Omron CX-Programmer project 新工程 (CX-Programmer 7.30)

# PLC 欧姆龙CP1H: CP1H X

## Global symbols (name address type ; comment)
D0 CHANNEL  ; 设定频率参考值
D1 CHANNEL  ; 设定加速时间1高字
D10 CHANNEL  ; 当前频率值-低字
D11 CHANNEL  ; 当前频率值-高字
D12 CHANNEL  ; 当前电流值
D2 CHANNEL  ; 设定加速时间1低字
D20 CHANNEL  ; 控制字

## Program 新程序1 (cyclic task 0)

### Section 段1

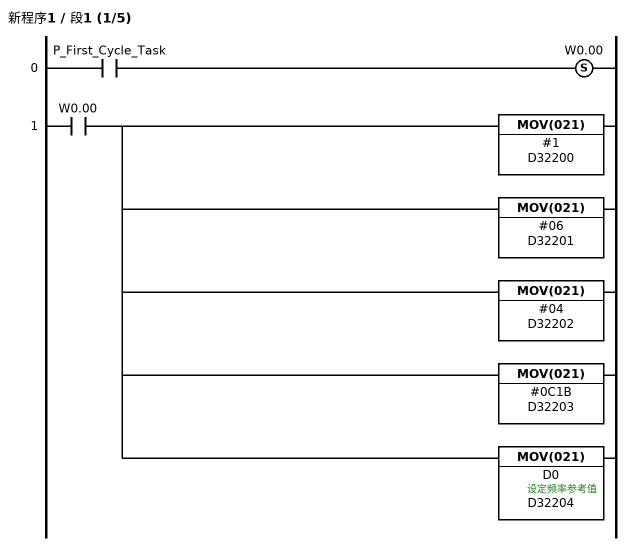
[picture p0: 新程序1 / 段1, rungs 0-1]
; rung 0
LD P_First_Cycle_Task
SET W0.00
; rung 1
LD W0.00
MOV(021) #1 D32200
MOV(021) #06 D32201
MOV(021) #04 D32202
MOV(021) #0C1B D32203
MOV(021) D0 D32204  ; 设定频率参考值

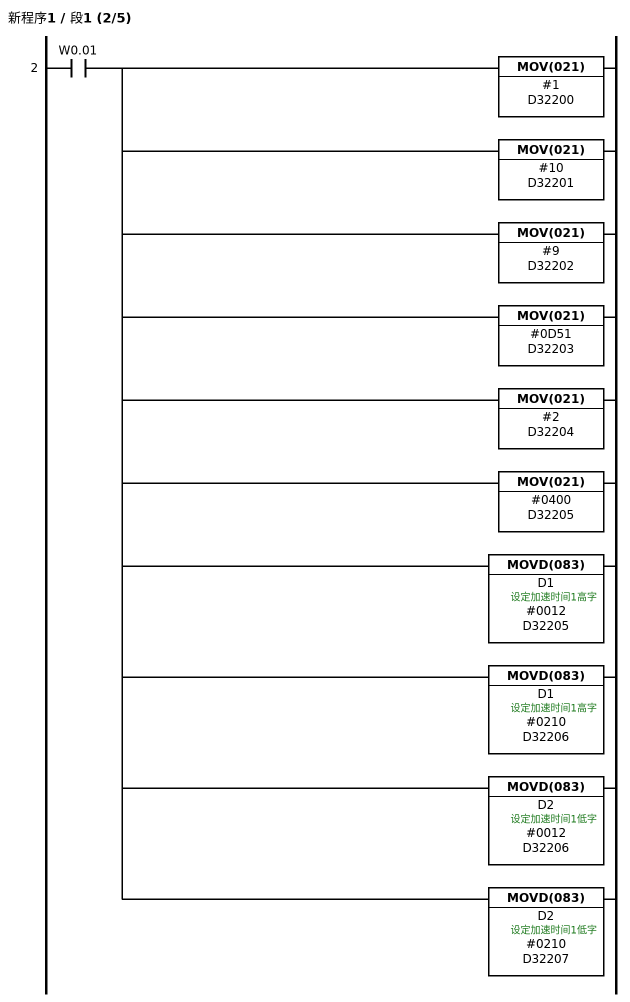
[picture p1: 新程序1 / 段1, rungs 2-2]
; rung 2
LD W0.01
MOV(021) #1 D32200
MOV(021) #10 D32201
MOV(021) #9 D32202
MOV(021) #0D51 D32203
MOV(021) #2 D32204
MOV(021) #0400 D32205
MOVD(083) D1 #0012 D32205  ; 设定加速时间1高字
MOVD(083) D1 #0210 D32206  ; 设定加速时间1高字
MOVD(083) D2 #0012 D32206  ; 设定加速时间1低字
MOVD(083) D2 #0210 D32207  ; 设定加速时间1低字

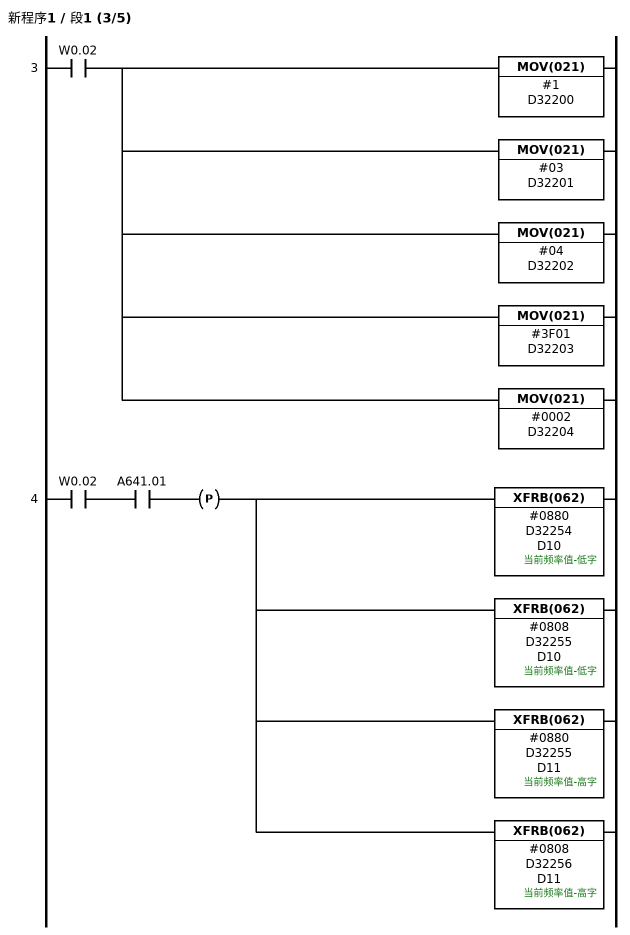
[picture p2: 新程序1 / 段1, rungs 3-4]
; rung 3
LD W0.02
MOV(021) #1 D32200
MOV(021) #03 D32201
MOV(021) #04 D32202
MOV(021) #3F01 D32203
MOV(021) #0002 D32204
; rung 4
LD W0.02
AND A641.01
UP(521)
XFRB(062) #0880 D32254 D10  ; 当前频率值-低字
XFRB(062) #0808 D32255 D10  ; 当前频率值-低字
XFRB(062) #0880 D32255 D11  ; 当前频率值-高字
XFRB(062) #0808 D32256 D11  ; 当前频率值-高字

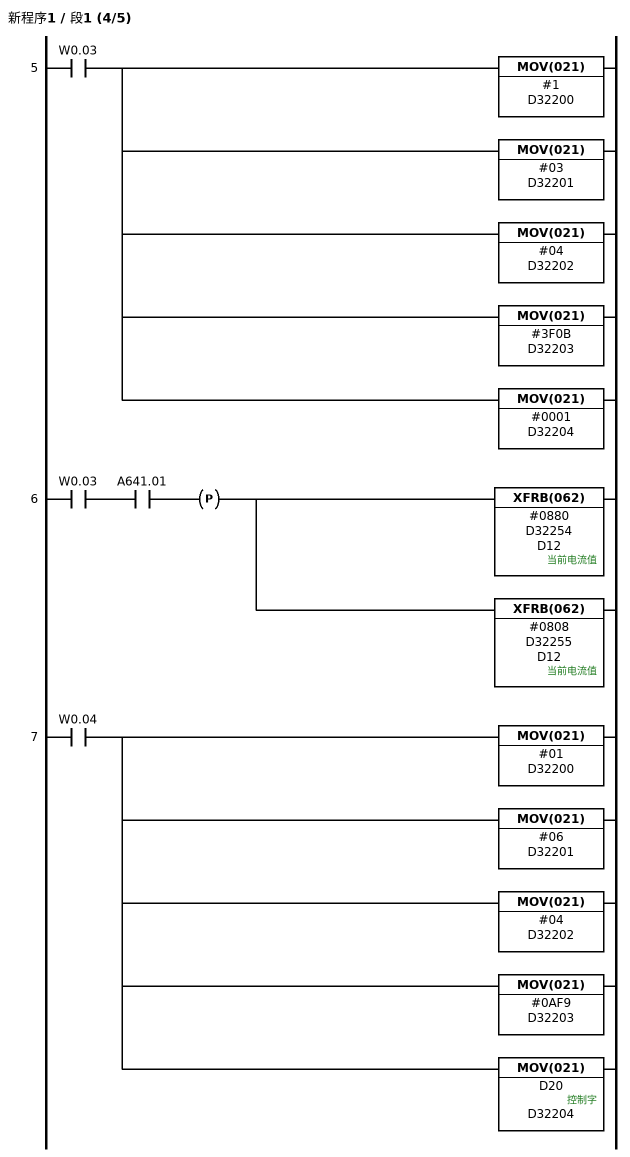
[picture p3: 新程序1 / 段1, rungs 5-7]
; rung 5
LD W0.03
MOV(021) #1 D32200
MOV(021) #03 D32201
MOV(021) #04 D32202
MOV(021) #3F0B D32203
MOV(021) #0001 D32204
; rung 6
LD W0.03
AND A641.01
UP(521)
XFRB(062) #0880 D32254 D12  ; 当前电流值
XFRB(062) #0808 D32255 D12  ; 当前电流值
; rung 7
LD W0.04
MOV(021) #01 D32200
MOV(021) #06 D32201
MOV(021) #04 D32202
MOV(021) #0AF9 D32203
MOV(021) D20 D32204  ; 控制字

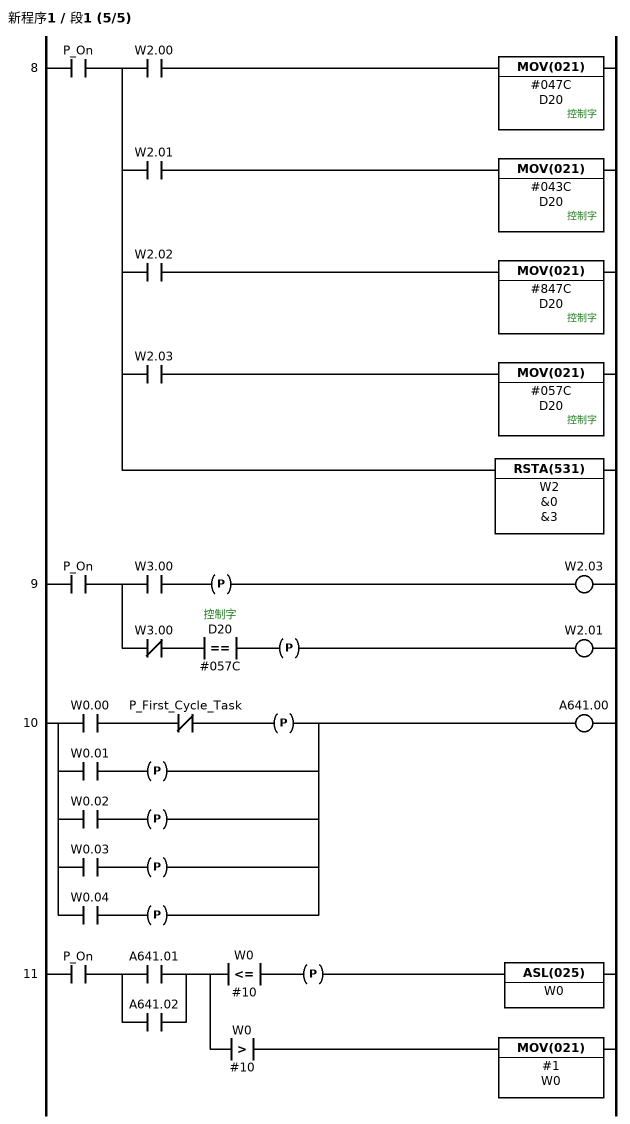
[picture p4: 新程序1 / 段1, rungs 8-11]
; rung 8
LD P_On
OUT TR0
AND W2.00
MOV(021) #047C D20  ; 控制字
LD TR0
AND W2.01
MOV(021) #043C D20  ; 控制字
LD TR0
AND W2.02
MOV(021) #847C D20  ; 控制字
LD TR0
AND W2.03
MOV(021) #057C D20  ; 控制字
LD TR0
RSTA(531) W2 &0 &3
; rung 9
LD P_On
OUT TR0
AND W3.00
UP(521)
OUT W2.03
LD TR0
ANDNOT W3.00
AND=(300) D20 #057C  ; 控制字
UP(521)
OUT W2.01
; rung 10
LD W0.00
ANDNOT P_First_Cycle_Task
UP(521)
LD W0.01
UP(521)
ORLD
LD W0.02
UP(521)
ORLD
LD W0.03
UP(521)
ORLD
LD W0.04
UP(521)
ORLD
OUT A641.00
; rung 11
LD P_On
LD A641.01
OR A641.02
ANDLD
OUT TR0
AND<=(315) W0 #10
UP(521)
ASL(025) W0
LD TR0
AND>(320) W0 #10
MOV(021) #1 W0
; rung 12
END(001)

### Section END
; rung 0
END(001)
